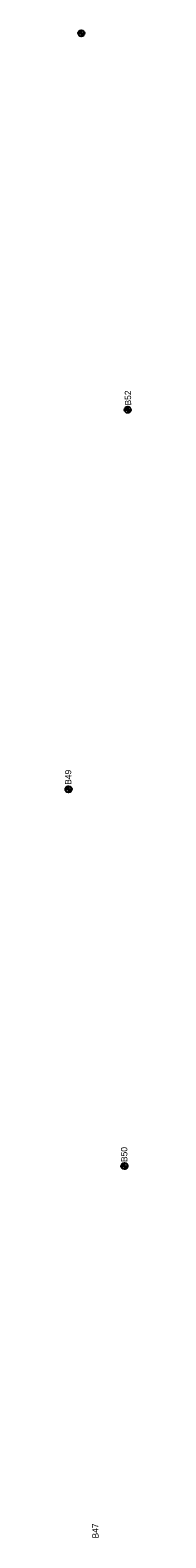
# Model space of a CAD drawing. Extents: x 327762 to 372792, y 127949 to 259367.
# Drawn here: x 360146 to 360251, y 155742 to 158137 of the extents above; entities that cross this region are included whole.
import ezdxf

# ---------------------------------------------------------------- set-up
doc = ezdxf.new("R2010")
doc.units = 0
for name, color, linetype in [('E_SOIL_BORE1 [KAPUR_CADDS_LEVELS]', 7, 'Continuous'), ('E_SOIL_BORE2 [KAPUR_CADDS_LEVELS]', 7, 'Continuous'), ('P_MARK', 7, 'Continuous')]:
    doc.layers.add(name, color=color, linetype=linetype)

msp = doc.modelspace()

# ---------------------------------------------------------------- linework, layer by layer
at = {"layer": 'P_MARK'}
for p, q in [((360166.9, 158132), (360176.9, 158132)), ((360171.9, 158137), (360171.9, 158127)), ((360240.6, 157534), (360250.6, 157534)), ((360245.6, 157539), (360245.6, 157529)), ((360151.6, 156936.2), (360151.6, 156926.2)), ((360146.6, 156931.2), (360156.6, 156931.2)), ((360240.4, 156337.7), (360240.4, 156327.7)), ((360235.4, 156332.7), (360245.4, 156332.7))]:
    msp.add_line(p, q, dxfattribs=at)
for centre in [(360171.9, 158132), (360245.6, 157534), (360151.6, 156931.2), (360240.4, 156332.7)]:
    msp.add_circle(centre, 5, dxfattribs=at)
for centre, radius, start, end in [((360171.9, 158132), 4.5, 89.9869, 179.9869), ((360171.9, 158132), 4, 89.9869, 179.9869), ((360171.9, 158132), 3.5, 89.9869, 179.9869), ((360171.9, 158132), 3, 89.9869, 179.9869), ((360171.9, 158132), 2.5, 89.9869, 179.9869), ((360171.9, 158132), 2, 89.9869, 179.9869), ((360171.9, 158132), 1.5, 89.9869, 179.9869), ((360171.9, 158132), 1, 89.9869, 179.9869), ((360171.9, 158132), 0.5, 89.9869, 179.9869), ((360171.9, 158132), 4.5, 269.9869, 359.9869), ((360171.9, 158132), 4, 269.9869, 359.9869), ((360171.9, 158132), 3.5, 269.9869, 359.9869), ((360171.9, 158132), 3, 269.9869, 359.9869), ((360171.9, 158132), 2.5, 269.9869, 359.9869), ((360171.9, 158132), 2, 269.9869, 359.9869), ((360171.9, 158132), 1.5, 269.9869, 359.9869), ((360171.9, 158132), 1, 269.9869, 359.9869), ((360171.9, 158132), 0.5, 269.9869, 359.9869), ((360245.6, 157534), 4.5, 89.9869, 179.9869), ((360245.6, 157534), 4, 89.9869, 179.9869), ((360245.6, 157534), 3.5, 89.9869, 179.9869), ((360245.6, 157534), 3, 89.9869, 179.9869), ((360245.6, 157534), 2.5, 89.9869, 179.9869), ((360245.6, 157534), 2, 89.9869, 179.9869), ((360245.6, 157534), 1.5, 89.9869, 179.9869), ((360245.6, 157534), 1, 89.9869, 179.9869), ((360245.6, 157534), 0.5, 89.9869, 179.9869), ((360245.6, 157534), 4.5, 269.9869, 359.9869), ((360245.6, 157534), 4, 269.9869, 359.9869), ((360245.6, 157534), 3.5, 269.9869, 359.9869), ((360245.6, 157534), 3, 269.9869, 359.9869), ((360245.6, 157534), 2.5, 269.9869, 359.9869), ((360245.6, 157534), 2, 269.9869, 359.9869), ((360245.6, 157534), 1.5, 269.9869, 359.9869), ((360245.6, 157534), 1, 269.9869, 359.9869), ((360245.6, 157534), 0.5, 269.9869, 359.9869), ((360151.6, 156931.2), 4.5, 89.9869, 179.9869), ((360151.6, 156931.2), 4, 89.9869, 179.9869), ((360151.6, 156931.2), 3.5, 89.9869, 179.9869), ((360151.6, 156931.2), 3, 89.9869, 179.9869), ((360151.6, 156931.2), 2.5, 89.9869, 179.9869), ((360151.6, 156931.2), 2, 89.9869, 179.9869), ((360151.6, 156931.2), 1.5, 89.9869, 179.9869), ((360151.6, 156931.2), 1, 89.9869, 179.9869), ((360151.6, 156931.2), 0.5, 89.9869, 179.9869), ((360151.6, 156931.2), 4.5, 269.9869, 359.9869), ((360151.6, 156931.2), 4, 269.9869, 359.9869), ((360151.6, 156931.2), 3.5, 269.9869, 359.9869), ((360151.6, 156931.2), 3, 269.9869, 359.9869), ((360151.6, 156931.2), 2.5, 269.9869, 359.9869), ((360151.6, 156931.2), 2, 269.9869, 359.9869), ((360151.6, 156931.2), 1.5, 269.9869, 359.9869), ((360151.6, 156931.2), 1, 269.9869, 359.9869), ((360151.6, 156931.2), 0.5, 269.9869, 359.9869), ((360240.4, 156332.7), 4.5, 89.9869, 179.9869), ((360240.4, 156332.7), 4, 89.9869, 179.9869), ((360240.4, 156332.7), 3.5, 89.9869, 179.9869), ((360240.4, 156332.7), 3, 89.9869, 179.9869), ((360240.4, 156332.7), 2.5, 89.9869, 179.9869), ((360240.4, 156332.7), 2, 89.9869, 179.9869), ((360240.4, 156332.7), 1.5, 89.9869, 179.9869), ((360240.4, 156332.7), 1, 89.9869, 179.9869), ((360240.4, 156332.7), 0.5, 89.9869, 179.9869), ((360240.4, 156332.7), 4.5, 269.9869, 359.9869), ((360240.4, 156332.7), 4, 269.9869, 359.9869), ((360240.4, 156332.7), 3.5, 269.9869, 359.9869), ((360240.4, 156332.7), 3, 269.9869, 359.9869), ((360240.4, 156332.7), 2.5, 269.9869, 359.9869), ((360240.4, 156332.7), 2, 269.9869, 359.9869), ((360240.4, 156332.7), 1.5, 269.9869, 359.9869), ((360240.4, 156332.7), 1, 269.9869, 359.9869), ((360240.4, 156332.7), 0.5, 269.9869, 359.9869)]:
    msp.add_arc(centre, radius, start, end, dxfattribs=at)

# ---------------------------------------------------------------- texts
at = {"layer": 'E_SOIL_BORE1 [KAPUR_CADDS_LEVELS]'}
for s, p in [('B50', (360245.1, 156339.2)), ('B47', (360199.3, 155741.2))]:
    msp.add_text(s, height=10, rotation=90.6368, dxfattribs=at).set_placement(p)
at = {"layer": 'E_SOIL_BORE2 [KAPUR_CADDS_LEVELS]'}
for s, p in [('B52', (360251.1, 157540.9)), ('B49', (360156.1, 156938.4))]:
    msp.add_text(s, height=10, rotation=90.6368, dxfattribs=at).set_placement(p)

doc.saveas('drawing.dxf')
